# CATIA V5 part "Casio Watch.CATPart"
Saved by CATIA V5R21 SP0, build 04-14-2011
Part number: CASIO Watch_AllCATPart
Bounding box of the stored display mesh (mm): x -23.5 to 28.68, y -58.854 to 58.854, z -4.5 to 8.5
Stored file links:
  C:\Users\Hooman\Desktop\CASIO Watch_AllCATPart.CATPart
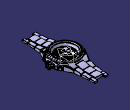
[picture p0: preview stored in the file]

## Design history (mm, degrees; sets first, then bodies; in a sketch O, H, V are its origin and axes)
Body1 (main body)
Body2 "Part2.1\\PartBody"
  Solid1: solid without history
Body3 "band1.1\\PartBody"
  Solid2 "Solid.1": solid without history
Body4 "band2.1\\PartBody"
  Solid3 "Solid.1": solid without history
Body5 "band3.1\\PartBody"
  Solid4 "Solid.1": solid without history
Body6 "Part1.1"
  Solid5 "Solid.1": solid without history
  Body7 "Part1.1\\Body.2"
    Solid6 "Solid.1": solid without history
  Add1 "Part1.1\\Body.2": tool Body7
Body8 "Part1.2\\PartBody"
  Solid7 "Solid.1": solid without history
Body9 "Part1.3\\PartBody"
  Solid8 "Solid.1": solid without history
Body10 "Part1.4\\PartBody"
  Solid9 "Solid.1": solid without history
Body11 "Part1.5"
  Solid10 "Solid.1": solid without history
  Body12 "Part1.5\\Body.2"
    Solid11 "Solid.1": solid without history
  Add2 "Part1.5\\Body.2": tool Body12
  Plane1: stored without definition
Body13 "Part1.6\\PartBody"
  Solid12 "Solid.1": solid without history
Body14 "Part1.7"
  Solid13 "Solid.1": solid without history
  Body15 "Part1.7\\Body.2"
    Solid14 "Solid.1": solid without history
  Add3 "Part1.7\\Body.2": tool Body15
Body16 "Part1.8"
  Solid15 "Solid.1": solid without history
  Body17 "Part1.8\\Body.2"
    Solid16 "Solid.1": solid without history
  Add4 "Part1.8\\Body.2": tool Body17
Body18 "Part1.9"
  Solid17 "Solid.1": solid without history
  Body19 "Part1.9\\Body.2"
    Solid18 "Solid.1": solid without history
  Add5 "Part1.9\\Body.2": tool Body19
  Plane2 "Plane.1": stored without definition
  Plane3 "Plane.2": stored without definition
Body20 "Part1.10\\PartBody"
  Solid19 "Solid.1": solid without history
Body21 "Part1.11\\PartBody"
  Solid20 "Solid.1": solid without history
Body22 "Part1.2.1"
  Solid21 "Solid.2": solid without history
  Body23 "Part1.2.1\\Body.2"
    Solid22 "Solid.1": solid without history
  Add6 "Part1.2.1\\Body.2": tool Body23
  Body24 "Part1.2.1\\Body.3"
    Solid23 "Solid.1": solid without history
  Add7 "Part1.2.1\\Body.3": tool Body24
Body25 "Part1.12"
  Solid24 "Solid.1": solid without history
  Body26 "Part1.12\\Body.2"
    Solid25 "Solid.1": solid without history
  Add8 "Part1.12\\Body.2": tool Body26
Body27 "Part1.14\\PartBody"
  Solid26 "Solid.1": solid without history
Body28 "Part1.15\\PartBody"
  Solid27 "Solid.1": solid without history
Body29 "Part1.16\\PartBody"
  Solid28 "Solid.1": solid without history
Body30 "Part1.17\\PartBody"
  Solid29 "Solid.1": solid without history
Body31 "Part1.18"
  Solid30 "Solid.1": solid without history
  Body32 "Part1.18\\Body.2"
    Solid31 "Solid.1": solid without history
  Add9 "Part1.18\\Body.2": tool Body32
  Body33 "Part1.18\\Body.4"
    Solid32 "Solid.1": solid without history
  Add10 "Part1.18\\Body.4": tool Body33
Body34 "Part1.19\\PartBody"
  Solid33 "Solid.1": solid without history
Body35 "Part1.20"
  Solid34 "Solid.1": solid without history
  Body36 "Part1.20\\Body.5"
    Solid35 "Solid.4": solid without history
  Add11 "Part1.20\\Body.5": tool Body36
  Body37 "Part1.20\\Body.6"
    Solid36 "Solid.5": solid without history
    Plane4 "Plane.2": stored without definition
  Add12 "Part1.20\\Body.6": tool Body37
Body38 "1.1\\PartBody"
  Solid37 "Solid.1": solid without history
Body39 "Part2.2\\PartBody"
  Solid38 "Solid.1": solid without history
Body40 "Part1.21\\PartBody"
  Solid39 "Solid.1": solid without history
  Set1 "Extracted Geometry (Thickness.2)"
    DatumSurface1 "Extract.2"
    DatumSurface2 "Offset.2"
  Set2 "Extracted Geometry (Thickness.1)"
    DatumSurface3 "Extract.1"
    DatumSurface4 "Offset.1"
Body41 "Part1.22\\PartBody"
  Solid40 "Solid.1": solid without history
Body42 "Part2.3\\PartBody"
  Solid41 "Solid.1": solid without history
Body43 "Part1.23\\PartBody"
  Solid42 "Solid.1": solid without history
Body44 "Part1.24\\PartBody"
  Solid43 "Solid.1": solid without history
Body45 "Part1.25\\PartBody"
  Solid44 "Solid.1": solid without history
Body46 "Part1.26\\PartBody"
  Solid45 "Solid.1": solid without history
Body47 "Part1.27"
  Solid46 "Solid.1": solid without history
  Body48 "Part1.27\\Body.2"
    Solid47 "Solid.1": solid without history
  Add13 "Part1.27\\Body.2": tool Body48
Body49 "Part1.29"
  Solid48 "Solid.1": solid without history
  Body50 "Part1.29\\Body.2"
    Solid49 "Solid.1": solid without history
  Add14 "Part1.29\\Body.2": tool Body50
Body51 "Part1.30"
  Solid50 "Solid.1": solid without history
  Body52 "Part1.30\\Body.2"
    Solid51 "Solid.1": solid without history
  Add15 "Part1.30\\Body.2": tool Body52
Body53 "Part1.28"
  Solid52 "Solid.1": solid without history
  Body54 "Part1.28\\Body.2"
    Solid53 "Solid.1": solid without history
  Add16 "Part1.28\\Body.2": tool Body54
Body55 "Part1.31"
  Solid54 "Solid.1": solid without history
  Body56 "Part1.31\\Body.2"
    Solid55 "Solid.1": solid without history
  Add17 "Part1.31\\Body.2": tool Body56
Body57 "Part1.32"
  Solid56 "Solid.1": solid without history
  Body58 "Part1.32\\Body.2"
    Solid57 "Solid.1": solid without history
  Add18 "Part1.32\\Body.2": tool Body58
Body59 "Part1.33"
  Solid58 "Solid.1": solid without history
  Body60 "Part1.33\\Body.2"
    Solid59 "Solid.1": solid without history
  Add19 "Part1.33\\Body.2": tool Body60
Body61 "Part1.34"
  Solid60 "Solid.1": solid without history
  Body62 "Part1.34\\Body.2"
    Solid61 "Solid.1": solid without history
  Add20 "Part1.34\\Body.2": tool Body62
Body63 "Part1.35\\PartBody"
  Solid62 "Solid.1": solid without history
  Set3 "Extracted Geometry (Thickness.2)"
    DatumSurface5 "Extract.2"
    DatumSurface6 "Offset.2"
  Set4 "Extracted Geometry (Thickness.1)"
    DatumSurface7 "Extract.1"
    DatumSurface8 "Offset.1"
Body64 "Part1.36"
  Solid63 "Solid.1": solid without history
  Body65 "Part1.36\\Body.2"
    Solid64 "Solid.1": solid without history
  Add21 "Part1.36\\Body.2": tool Body65
Body66 "Part1.37"
  Solid65 "Solid.1": solid without history
  Body67 "Part1.37\\Body.2"
    Solid66 "Solid.1": solid without history
  Add22 "Part1.37\\Body.2": tool Body67
Body68 "Part1.38"
  Solid67 "Solid.1": solid without history
  Body69 "Part1.38\\Body.2"
    Solid68 "Solid.1": solid without history
  Add23 "Part1.38\\Body.2": tool Body69
Body70 "band1.2\\PartBody"
  Solid69 "Solid.1": solid without history
Body71 "Part2.4\\PartBody"
  Solid70 "Solid.1": solid without history
Body72 "Part2.5\\PartBody"
  Solid71 "Solid.1": solid without history
Body73 "Part2.6\\PartBody"
  Solid72 "Solid.1": solid without history
Body74 "band2.2\\PartBody"
  Solid73 "Solid.1": solid without history
Body75 "Part2.7\\PartBody"
  Solid74 "Solid.1": solid without history
Body76 "Part2.8\\PartBody"
  Solid75 "Solid.1": solid without history
Body77 "band3.2\\PartBody"
  Solid76 "Solid.1": solid without history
